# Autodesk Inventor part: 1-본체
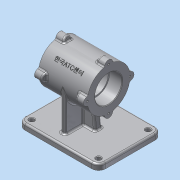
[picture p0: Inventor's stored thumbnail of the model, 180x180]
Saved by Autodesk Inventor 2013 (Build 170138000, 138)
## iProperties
Created: 2015-12
Part Number: 1-본체
Material: 알루미늄 6061
Document SubType Name: Modeling
Designer: dgall
Density: 1 g/cm^3
Author: dgall
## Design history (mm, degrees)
sketch "스케치1"
  geometry: L1 (-70, 55)-(70, 55); L2 (70, 55)-(70, -55); L3 (70, -55)-(-70, -55); L4 (-70, -55)-(-70, 55); 3 further points
  constraints: 8 end point, 2 midpoint, 2 parallel, 1 horizontal, 1 horizontal alignment, 1 perpendicular, 1 vertical alignment
  dimensions: "d0" = 140 distance of L1.start L1.end; "d2" = 110 distance between parallel lines of L3 L1
extrude "돌출1" new body sketch "스케치1" distance "d3" = 10; taper "d4" = 0 deg
node "작업 평면1"
node "작업 평면2"
node "작업 평면3"
fillet "모깎기1" dims "d57" = 12
sketch "스케치10"
  geometry: C1 r 4 at (58, -43); C2 r 4 at (58, 43); C3 r 4 at (-58, -43); C4 r 4 at (-58, 43); A1 r 12 centre (-58, -43) between (-70, -43) and (-58, -55) reference; A2 r 12 centre (58, -43) between (58, -55) and (70, -43) reference; A3 r 12 centre (58, 43) between (70, 43) and (58, 55) reference; A4 r 12 centre (-58, 43) between (-58, 55) and (-70, 43) reference; 1 further point
  constraints: 4 centre point, 4 coincident, 3 equal radius
  dimensions: "d58" = 8 diameter of C1
extrude "돌출9" cut sketch "스케치10" stored distance "d59" = 12; taper "d60" = 0 deg
fillet "모깎기6" dims "d65" = 3
node "작업 평면6"
node "작업 평면10"
node "작업 평면15"
node "작업 평면16"
chamfer "모따기2" distance "d125" = 1; stored, may be unused: second distance "d126" = 2, angle "d127" = 45 deg
node "작업 평면24"
sketch "스케치17"
  geometry: L1 (0, 98)-(0, 86) reference; C1 r 37 at (-80, 43); 1 further point
  constraints: 1 centre point, 1 horizontal alignment
  dimensions: "d134" = 74 diameter of C1; "d135" = 80 distance from line of L1 C1.centre
extrude "돌출12" join sketch "스케치17" stored distance "d136" = 85; taper "d137" = 0 deg
sketch "스케치18"
  geometry: A1 r 7 centre (-37, 0) between (-36.338, 6.969) and (-36.338, -6.969); A2 r 7 centre (0, -37) between (-6.969, -36.338) and (6.969, -36.338); A3 r 7 centre (0, 37) between (6.969, 36.338) and (-6.969, 36.338); A4 r 7 centre (37, 0) between (36.338, -6.969) and (36.338, 6.969); 2 further points
  constraints: 8 point on circle, 4 centre point, 3 equal radius, 2 horizontal alignment, 2 vertical alignment, 13 other
  dimensions: "d138" = 7 radius of A1
extrude "돌출13" join sketch "스케치18" distance "d139" = 15; taper "d140" = 0 deg
node "작업 평면25"
node "작업 평면26"
feature "면 기울기15" dims angle "d141" = 20 deg
feature "면 기울기16" dims angle "d142" = 20 deg
node "작업 평면27"
node "작업 평면28"
feature "면 기울기17" dims angle "d143" = 20 deg
feature "면 기울기18" dims angle "d144" = 20 deg
feature "면 기울기19" dims angle "d145" = 20 deg
feature "면 기울기20" dims angle "d146" = 20 deg
node "작업 평면29"
feature "면 기울기21" dims angle "d147" = 20 deg
feature "면 기울기22" dims angle "d148" = 20 deg
fillet "모깎기20" dims "d149" = 3
fillet "모깎기21" dims "d150" = 3
sketch "스케치19"
  geometry: A1 r 7 centre (80, 6) between (73.111, 4.761) and (86.889, 4.761) reference; A2 r 7 centre (117, 43) between (118.239, 36.111) and (118.239, 49.889) reference; A3 r 7 centre (80, 80) between (86.889, 81.239) and (73.111, 81.239) reference; A4 r 7 centre (43, 43) between (41.761, 49.889) and (41.761, 36.111) reference; 1 further point
hole "구멍4" sketch "스케치19" at (117, 43), (80, 6), (43, 43), (80, 80) diameter "d151" = 3.242; stored, may be unused: countersink angle "d155" = 90 deg, drill point angle "d157" = 118 deg; dims "d152" = 9, "d153" = 4, "d154" = 2, "d156" = 11
node "작업 평면30"
node "작업 평면31"
hole "구멍5" diameter "d160" = 42; stored, may be unused: countersink angle "d164" = 90 deg, drill point angle "d166" = 118 deg; dims "d158" = 10, "d159" = 10, "d161" = 9, "d162" = 47, "d163" = 22, "d165" = 11
sketch "스케치20"
  geometry: C1 r 21 at (80, 43) reference; C2 r 23.5 at (80, 43); A1 r 37 centre (80, 43) between (70.896, 78.863) and (44.137, 52.104) reference; 1 further point
  constraints: 1 centre point, 1 coincident
  dimensions: "d167" = 47 diameter of C2
extrude "돌출14" cut sketch "스케치20" distance "d168" = 22; taper "d169" = 0 deg
chamfer "모따기3" distance "d170" = 1; stored, may be unused: second distance "d171" = 2, angle "d172" = 45 deg
node "작업 평면32"
sketch "스케치21"
  geometry: L1 (-125, 10)-(9, 10) reference; L2 (12, 7)-(12, 0) reference; L3 (12, 0)-(-128, 0) reference; L4 (-128, 0)-(-128, 7) reference; L5 (-22.601, 43)-(-73.399, 43) reference; L6 (-76.218, 41.026)-(-77.329, 37.974) reference; L7 (-80.148, 36)-(-90.5, 36) reference; L8 (-90.5, 36)-(-90.5, 41.379) reference; L9 (-90.5, 41.379)-(-79.5, 41.379) reference; L10 (-79.5, 41.379)-(-78.526, 43) reference; L11 (-78.526, 43)-(-79.5, 44.621) reference; L12 (-79.5, 44.621)-(-90.5, 44.621) reference; L13 (-90.5, 44.621)-(-90.5, 55.5) reference; L14 (-90.5, 55.5)-(-89.5, 56.5) reference; L15 (-89.5, 56.5)-(-68.5, 56.5) reference; L16 (-68.5, 56.5)-(-68.5, 59) reference; L17 (-68.5, 59)-(-27.5, 59) reference; L18 (-27.5, 59)-(-27.5, 56.5) reference; L19 (-27.5, 56.5)-(-6.5, 56.5) reference; L20 (-6.5, 56.5)-(-5.5, 55.5) reference; L21 (-5.5, 55.5)-(-5.5, 44.621) reference; L22 (-5.5, 44.621)-(-16.5, 44.621) reference; L23 (-16.5, 44.621)-(-17.474, 43) reference; L24 (-17.474, 43)-(-16.5, 41.379) reference; L25 (-16.5, 41.379)-(-5.5, 41.379) reference; L26 (-5.5, 41.379)-(-5.5, 36) reference; L27 (-5.5, 36)-(-15.852, 36) reference; L28 (-18.671, 37.974)-(-19.782, 41.026) reference; L29 (-19.782, 118.974)-(-18.671, 122.026) reference; L30 (-15.852, 124)-(-5.5, 124) reference; L31 (-5.5, 124)-(-5.5, 118.621) reference; L32 (-5.5, 118.621)-(-16.5, 118.621) reference; L33 (-16.5, 118.621)-(-17.474, 117) reference; L34 (-17.474, 117)-(-16.5, 115.379) reference; L35 (-16.5, 115.379)-(-5.5, 115.379) reference; L36 (-5.5, 115.379)-(-5.5, 104.5) reference; L37 (-5.5, 104.5)-(-6.5, 103.5) reference; L38 (-6.5, 103.5)-(-27.5, 103.5) reference; L39 (-27.5, 103.5)-(-27.5, 101) reference; L40 (-27.5, 101)-(-68.5, 101) reference; L41 (-68.5, 101)-(-68.5, 103.5) reference; L42 (-68.5, 103.5)-(-89.5, 103.5) reference; L43 (-89.5, 103.5)-(-90.5, 104.5) reference; L44 (-90.5, 104.5)-(-90.5, 115.379) reference; L45 (-90.5, 115.379)-(-79.5, 115.379) reference; L46 (-79.5, 115.379)-(-78.526, 117) reference; L47 (-78.526, 117)-(-79.5, 118.621) reference; L48 (-79.5, 118.621)-(-90.5, 118.621) reference; L49 (-90.5, 118.621)-(-90.5, 124) reference; L50 (-90.5, 124)-(-80.148, 124) reference; L51 (-77.329, 122.026)-(-76.218, 118.974) reference; L52 (-73.399, 117)-(-22.601, 117) reference; L53 (-48, 117)-(-48, 0); L54 (-73, 10)-(-68.015, 50.603); L55 (-68.015, 50.603)-(-27.985, 50.603); L56 (-27.985, 50.603)-(-23, 10); L57 (-73, 10)-(-23, 10); A1 r 3 centre (9, 7) between (12, 7) and (9, 10) reference; A2 r 3 centre (-125, 7) between (-125, 10) and (-128, 7) reference; 1 further point
  constraints: 10 end point, 3 point on line, 2 perpendicular, 1 collinear, 1 midpoint, 8 other
  dimensions: "d173" = 25 distance from line of L53 L54.start; "d175" = 50 distance of L56.end L54.start; "d176" = 97 deg angle of L54 L1; "d177" = 97 deg angle of L1 L56; "d178" = 40.60278 distance between parallel lines of L1 L55
extrude "돌출15" join sketch "스케치21" stored distance "d179" = 12; taper "d180" = 0 deg
node "작업 평면33"
sketch "스케치22"
  geometry: L1 (-43.49, 49)-(-10, 49) reference; L2 (-10, 49)-(-10, 95) reference; L3 (-7, 98)-(0, 98) reference; L4 (0, 98)-(0, -12) reference; L5 (0, -12)-(-7, -12) reference; L6 (-10, -9)-(-10, 37) reference; L7 (-10, 37)-(-43.49, 37) reference; L8 (-80, 6)-(-10, 6); L9 (-80, 80)-(-10, 80); C1 r 21 at (-80, 43) reference; A1 r 3 centre (-7, 95) between (-7, 98) and (-10, 95) reference; A2 r 3 centre (-7, -9) between (-10, -9) and (-7, -12) reference; A3 r 37 centre (-80, 43) between (-43.49, 49) and (-43.49, 37) reference; 1 further point
  constraints: 4 end point, 2 perpendicular, 2 point on circle, 2 point on line, 2 tangent
extrude "돌출16" join sketch "스케치22" stored distance "d182" = 8; taper "d183" = 0 deg
fillet "모깎기22" dims "d184" = 3
fillet "모깎기23" dims "d185" = 3
node "작업 평면34"
sketch "스케치23"
  geometry: L1 (-13, 37)-(-41.026, 37) reference; L2 (-41.026, 49)-(-13, 49) reference; L3 (-10, 52)-(-10, 95) reference; L4 (-7, 98)-(0, 98) reference; L5 (0, 98)-(0, -12) reference; L6 (0, -12)-(-7, -12) reference; L7 (-10, -9)-(-10, 34) reference; L8 (0, 43)-(-80, 43); L9 (-80, 43)-(-106.163, 16.837); C1 r 21 at (-80, 43) reference; A1 r 3 centre (-13, 34) between (-10, 34) and (-13, 37) reference; A2 r 3 centre (-41.026, 34) between (-41.026, 37) and (-43.949, 34.675) reference; A3 r 37 centre (-80, 43) between (-43.949, 51.325) and (-43.949, 34.675) reference; A4 r 3 centre (-41.026, 52) between (-43.949, 51.325) and (-41.026, 49) reference; A5 r 3 centre (-13, 52) between (-13, 49) and (-10, 52) reference; A6 r 3 centre (-7, 95) between (-7, 98) and (-10, 95) reference; A7 r 3 centre (-7, -9) between (-10, -9) and (-7, -12) reference
  constraints: 4 end point, 1 perpendicular, 1 point on circle
  dimensions: "d186" = 135 deg angle of L8 L9
  node "절단 모서리 투영7"
node "작업 평면35"
sketch "스케치24"
  geometry: L1 (-52.5, 0)-(32.5, 0) reference; L2 (-52.5, 0)-(32.5, 0) reference; L3 (-58, -90.51)-(58, -90.51) reference; L4 (-58, -95.459)-(-58, -90.51) reference; L5 (58, -95.459)-(-58, -95.459) reference; L6 (58, -90.51)-(58, -95.459) reference; L7 (-52.5, 18.921)-(-52.5, -18.921) reference; 3 further points
  constraints: 1 horizontal alignment, 1 midpoint, 1 other
  dimensions: "d187" = 42.5 distance from line of point (-10, 0) L7
feature "엠보싱2" sketch "스케치24" dims "d188" = 0.5, "d189" = 0
node "솔리드1"
sketch "스케치12"
  geometry: L1 (10, 95)-(10, -9) reference; L2 (7, -12)-(0, -12) reference; L3 (0, -12)-(0, 98) reference; L4 (0, 98)-(7, 98) reference; L5 (0, 43)-(80, 43); L6 (80, 43)-(106.163, 69.163); A1 r 3 centre (7, 95) between (10, 95) and (7, 98) reference; A2 r 3 centre (7, -9) between (7, -12) and (10, -9) reference
  constraints: 4 end point, 1 parallel
  dimensions: "d96" = 135 deg angle of L6 L5
mirror "대칭2"
mirror "대칭3"
mirror "대칭4"
node "투영된 루프1"
node "절단 모서리 투영4"
node "절단 모서리 투영5"
node "절단 모서리 투영6"
node "절단 모서리 투영8"
node "절단 모서리 투영9"
